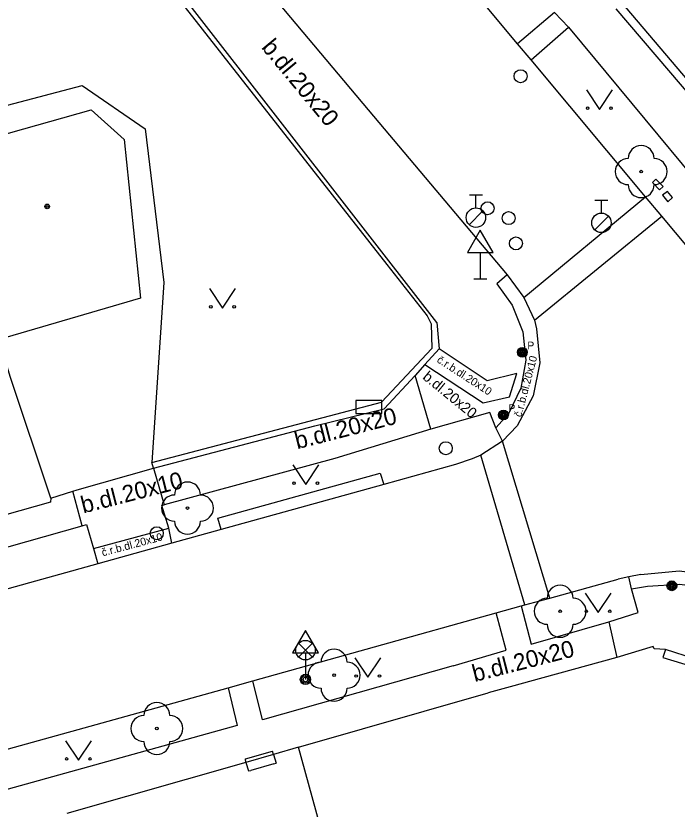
# Model space of a CAD drawing. Extents: x -595546 to -593986, y -1160845 to -1159202.
# Drawn here: x -595239.81 to -595214.37, y -1160581.47 to -1160550.96 of the extents above; entities that cross this region are included whole.
import ezdxf

# ---------------------------------------------------------------- set-up
doc = ezdxf.new("R2010")
doc.units = 0
for name, color, linetype in [('Level 22', 7, 'Continuous'), ('Level 24', 7, 'Continuous'), ('Level 28', 7, 'Continuous'), ('Level 33', 7, 'Continuous'), ('Level 34', 7, 'Continuous'), ('Level 36', 7, 'Continuous'), ('Level 39', 7, 'Continuous'), ('slaboproud - povrch.  znaky a tel. budka skut. velikost', 7, 'Continuous'), ('TM - budovy zdene_ betonove - NP', 7, 'Continuous'), ('TM - budovy zdene_ betonove - VP', 7, 'Continuous'), ('TM - chodniky - VP', 7, 'Continuous'), ('TM - komunikace - VP', 7, 'Continuous'), ('TM - letecke snimky - pomocna linie', 7, 'Continuous'), ('TM - plot drateny_ kovovy - VP', 7, 'Continuous'), ('TM - podezdivka plotu - VP', 7, 'Continuous'), ('TM - popis povrchu', 7, 'Continuous'), ('TM - rozhrani mezi zpev. plochami mezi sebou - VP', 7, 'Continuous'), ('TM - rozhrani ploch obecne - VP', 7, 'Continuous'), ('TM - vjezd na pozemek', 7, 'Continuous'), ('TM - vstup do budovy - zdene_ betonove', 7, 'Continuous'), ('TM - vstup do budovy - zdene_ betonove  - shora neviditelny', 7, 'Continuous'), ('Vrstva 34', 7, 'Continuous')]:
    doc.layers.add(name, color=color, linetype=linetype)

msp = doc.modelspace()

# ---------------------------------------------------------------- linework, layer by layer
at = {"layer": 'Level 22'}
for centre in [(-595215.75, -1160556.95), (-595233.21, -1160569.89), (-595218.87, -1160573.86), (-595227.57, -1160576.32), (-595234.39, -1160578.37)]:
    msp.add_circle(centre, 0.05, dxfattribs=at)
for centre, start, end in [((-595215.75, -1160556.45), 0, 180), ((-595216.25, -1160556.95), 90, 270), ((-595215.25, -1160556.95), 270, 90), ((-595215.75, -1160557.45), 180, 0), ((-595233.21, -1160569.39), 0, 180), ((-595233.71, -1160569.89), 90, 270), ((-595232.71, -1160569.89), 270, 90), ((-595233.21, -1160570.39), 180, 0), ((-595218.87, -1160573.36), 0, 180), ((-595219.37, -1160573.86), 90, 270), ((-595218.37, -1160573.86), 270, 90), ((-595218.87, -1160574.36), 180, 0), ((-595227.57, -1160575.82), 0, 180), ((-595228.07, -1160576.32), 90, 270), ((-595227.07, -1160576.32), 270, 90), ((-595227.57, -1160576.82), 180, 0), ((-595234.39, -1160577.87), 0, 180), ((-595234.89, -1160578.37), 90, 270), ((-595233.89, -1160578.37), 270, 90), ((-595234.39, -1160578.87), 180, 0)]:
    msp.add_arc(centre, 0.5, start, end, dxfattribs=at)
at = {"layer": 'Level 24'}
msp.add_lwpolyline([(-595226.737, -1160566.258), (-595225.737, -1160566.258), (-595225.737, -1160565.758), (-595226.737, -1160565.758)], close=True, dxfattribs=at)
at = {"layer": 'Level 28'}
for p, q in [((-595222.36, -1160557.845), (-595221.86, -1160557.845)), ((-595222.11, -1160558.345), (-595222.11, -1160557.845)), ((-595217.53, -1160558.045), (-595217.03, -1160558.045)), ((-595217.28, -1160558.545), (-595217.28, -1160558.045)), ((-595222.368, -1160558.992), (-595221.838, -1160558.462)), ((-595217.538, -1160559.192), (-595217.008, -1160558.662))]:
    msp.add_line(p, q, dxfattribs=at)
for centre, radius in [((-595220.39, -1160553.28), 0.25), ((-595221.66, -1160558.36), 0.25), ((-595222.11, -1160558.72), 0.375), ((-595220.85, -1160558.74), 0.25), ((-595217.28, -1160558.92), 0.375), ((-595220.57, -1160559.71), 0.25), ((-595223.27, -1160567.59), 0.25), ((-595234.39, -1160570.86), 0.25)]:
    msp.add_circle(centre, radius, dxfattribs=at)
at = {"layer": 'Level 33'}
for p, q in [((-595228.935, -1160575.62), (-595228.405, -1160575.09)), ((-595228.935, -1160575.09), (-595228.405, -1160575.62)), ((-595228.67, -1160575.73), (-595228.67, -1160576.48))]:
    msp.add_line(p, q, dxfattribs=at)
for centre, radius in [((-595228.67, -1160575.355), 0.375), ((-595228.67, -1160576.48), 0.2), ((-595228.67, -1160576.48), 0.145), ((-595228.67, -1160576.48), 0.0876)]:
    msp.add_circle(centre, radius, dxfattribs=at)
at = {"layer": 'Level 34'}
for p, q in [((-595221.94, -1160560.062), (-595221.94, -1160561.08)), ((-595222.19, -1160561.08), (-595221.69, -1160561.08)), ((-595228.67, -1160575.462), (-595228.67, -1160576.48))]:
    msp.add_line(p, q, dxfattribs=at)
for points in [[(-595222.44, -1160560.062), (-595221.44, -1160560.062), (-595221.94, -1160559.196)], [(-595229.17, -1160575.462), (-595228.17, -1160575.462), (-595228.67, -1160574.596)]]:
    msp.add_lwpolyline(points, close=True, dxfattribs=at)
at = {"layer": 'Level 36'}
for points in [[(-595217.86, -1160553.81), (-595217.36, -1160554.56), (-595216.86, -1160553.81)], [(-595232.36, -1160561.45), (-595231.86, -1160562.2), (-595231.36, -1160561.45)], [(-595229.16, -1160568.23), (-595228.66, -1160568.98), (-595228.16, -1160568.23)], [(-595217.91, -1160573.16), (-595217.41, -1160573.91), (-595216.91, -1160573.16)], [(-595226.77, -1160575.65), (-595226.27, -1160576.4), (-595225.77, -1160575.65)], [(-595237.91, -1160578.84), (-595237.41, -1160579.59), (-595236.91, -1160578.84)]]:
    msp.add_lwpolyline(points, dxfattribs=at)
for centre in [(-595217.81, -1160554.51), (-595216.911, -1160554.51), (-595232.31, -1160562.15), (-595231.411, -1160562.15), (-595229.11, -1160568.93), (-595228.211, -1160568.93), (-595217.86, -1160573.86), (-595216.961, -1160573.86), (-595226.72, -1160576.35), (-595225.821, -1160576.35), (-595237.86, -1160579.54), (-595236.961, -1160579.54)]:
    msp.add_circle(centre, 0.05, dxfattribs=at)
at = {"layer": 'Level 39'}
for radius in [0.09, 0.0398]:
    msp.add_circle((-595238.61, -1160558.29), radius, dxfattribs=at)
at = {"layer": 'slaboproud - povrch.  znaky a tel. budka skut. velikost'}
for points in [[(-595215.19, -1160557.24), (-595215.32, -1160557.37)], [(-595215.32, -1160557.37), (-595215.04, -1160557.65)], [(-595214.91, -1160557.52), (-595215.19, -1160557.24)], [(-595215.04, -1160557.65), (-595214.91, -1160557.52)], [(-595214.74, -1160557.71), (-595214.93, -1160557.86)], [(-595214.93, -1160557.86), (-595214.73, -1160558.11)], [(-595214.54, -1160557.94), (-595214.74, -1160557.71)], [(-595214.73, -1160558.11), (-595214.54, -1160557.94)]]:
    msp.add_lwpolyline(points, dxfattribs=at)
at = {"layer": 'TM - budovy zdene_ betonove - NP'}
for points in [[(-595214.82, -1160575.33), (-595214.92, -1160575.64)], [(-595229.9, -1160579.37), (-595229.8, -1160579.7)], [(-595230.96, -1160579.67), (-595230.86, -1160580)], [(-595229.89, -1160579.73), (-595229.8, -1160579.7)], [(-595230.86, -1160580), (-595230.77, -1160579.98)]]:
    msp.add_lwpolyline(points, dxfattribs=at)
at = {"layer": 'TM - budovy zdene_ betonove - VP'}
for points in [[(-595238.47, -1160569.51), (-595240.03, -1160564.83), (-595240.47, -1160563.41)], [(-595238.47, -1160569.51), (-595238.48, -1160569.66)], [(-595238.48, -1160569.66), (-595246.66, -1160571.97)], [(-595215.29, -1160575.21), (-595216.69, -1160575.64)], [(-595215.25, -1160575.3), (-595215.29, -1160575.21)], [(-595214.82, -1160575.33), (-595215.25, -1160575.3)], [(-595213.7, -1160575.69), (-595214.82, -1160575.33)], [(-595216.69, -1160575.64), (-595219.54, -1160576.42)], [(-595220.79, -1160576.77), (-595221.64, -1160577)], [(-595228.94, -1160579.09), (-595221.64, -1160577)], [(-595228.94, -1160579.09), (-595229.9, -1160579.37)], [(-595226.01, -1160589.72), (-595228.94, -1160579.09)], [(-595229.9, -1160579.37), (-595230.96, -1160579.67)], [(-595230.96, -1160579.67), (-595237.85, -1160581.64)]]:
    msp.add_lwpolyline(points, dxfattribs=at)
at = {"layer": 'TM - chodniky - VP'}
for points in [[(-595219.08, -1160550.83), (-595220.51, -1160552.04)], [(-595219.99, -1160552.65), (-595218.55, -1160551.4)], [(-595218.55, -1160551.4), (-595210.74, -1160560.81)], [(-595221.58, -1160566.22), (-595223.85, -1160566.86)], [(-595221.34, -1160566.8), (-595221.58, -1160566.22)], [(-595221.09, -1160567.32), (-595221.34, -1160566.8)], [(-595223.85, -1160566.86), (-595227.54, -1160567.98)], [(-595227.54, -1160567.98), (-595234.11, -1160569.76)], [(-595234.2, -1160569.79), (-595234.11, -1160569.76)], [(-595233.93, -1160570.66), (-595234.2, -1160569.79)], [(-595247.15, -1160573.37), (-595237.26, -1160570.57)], [(-595237.26, -1160570.57), (-595237.1, -1160570.52)], [(-595237.1, -1160570.52), (-595236.83, -1160571.44)], [(-595233.81, -1160571.24), (-595233.93, -1160570.66)], [(-595236.83, -1160571.44), (-595236.66, -1160572.03)], [(-595216.12, -1160573), (-595216.23, -1160572.54)], [(-595215.87, -1160573.91), (-595216.12, -1160573)], [(-595220.37, -1160573.65), (-595219.98, -1160575.12)], [(-595220.94, -1160575.36), (-595221.33, -1160573.92)], [(-595217, -1160574.27), (-595215.87, -1160573.91)], [(-595219.98, -1160575.12), (-595217, -1160574.27)], [(-595222.98, -1160575.96), (-595220.94, -1160575.36)], [(-595222.98, -1160575.96), (-595230.32, -1160578.03)], [(-595230.32, -1160578.03), (-595230.69, -1160576.53)], [(-595231.65, -1160576.8), (-595231.3, -1160578.25)], [(-595231.3, -1160578.25), (-595243.44, -1160581.63)]]:
    msp.add_lwpolyline(points, dxfattribs=at)
at = {"layer": 'TM - komunikace - VP'}
for points in [[(-595232.03, -1160547.7), (-595226.26, -1160554.57)], [(-595220.51, -1160552.04), (-595221.87, -1160550.41)], [(-595219.99, -1160552.65), (-595220.51, -1160552.04)], [(-595215.58, -1160557.92), (-595219.99, -1160552.65)], [(-595226.26, -1160554.57), (-595220.91, -1160560.92)], [(-595214.95, -1160558.67), (-595215.58, -1160557.92)], [(-595212.2, -1160561.96), (-595214.95, -1160558.67)], [(-595220.91, -1160560.92), (-595220.27, -1160561.79)], [(-595220.27, -1160561.79), (-595219.86, -1160562.66)], [(-595219.86, -1160562.66), (-595219.78, -1160563), (-595219.65, -1160564.3), (-595219.91, -1160565.58), (-595220.52, -1160566.73)], [(-595220.52, -1160566.73), (-595221.09, -1160567.32)], [(-595221.09, -1160567.32), (-595221.92, -1160567.86)], [(-595222.26, -1160568), (-595222.9, -1160568.21)], [(-595221.92, -1160567.86), (-595222.26, -1160568)], [(-595222.9, -1160568.21), (-595225.65, -1160568.98)], [(-595225.65, -1160568.98), (-595231.92, -1160570.72)], [(-595231.92, -1160570.72), (-595233.81, -1160571.24)], [(-595233.81, -1160571.24), (-595236.66, -1160572.03)], [(-595236.66, -1160572.03), (-595240.3, -1160573.05)], [(-595215.76, -1160572.44), (-595214.29, -1160572.3), (-595212.83, -1160572.48)], [(-595219.27, -1160573.35), (-595216.63, -1160572.62)], [(-595216.23, -1160572.54), (-595216.63, -1160572.62)], [(-595215.76, -1160572.44), (-595216.23, -1160572.54)], [(-595220.23, -1160573.61), (-595219.27, -1160573.35)], [(-595221.33, -1160573.92), (-595220.37, -1160573.65)], [(-595220.37, -1160573.65), (-595220.23, -1160573.61)], [(-595230.69, -1160576.53), (-595221.33, -1160573.92)], [(-595231.65, -1160576.8), (-595230.69, -1160576.53)], [(-595243.8, -1160580.18), (-595231.65, -1160576.8)]]:
    msp.add_lwpolyline(points, dxfattribs=at)
at = {"layer": 'TM - letecke snimky - pomocna linie'}
for points in [[(-595243.02, -1160555.15), (-595237.26, -1160553.64), (-595234.84, -1160555.31), (-595234.12, -1160561.22), (-595234.58, -1160568.14)], [(-595242.7, -1160556.2), (-595236.92, -1160554.57), (-595235.65, -1160555.71), (-595235.02, -1160561.82), (-595240.47, -1160563.41)]]:
    msp.add_lwpolyline(points, dxfattribs=at)
at = {"layer": 'TM - plot drateny_ kovovy - VP'}
for points in [[(-595239.75, -1160542.44), (-595238.3, -1160544.26), (-595225.54, -1160560.52)], [(-595211.49, -1160556.33), (-595216.36, -1160550.6), (-595213.17, -1160547.65)], [(-595225.54, -1160560.52), (-595223.98, -1160562.5)], [(-595223.98, -1160562.5), (-595223.83, -1160562.81), (-595223.81, -1160563.75), (-595225.74, -1160565.82)], [(-595234.58, -1160568.14), (-595225.74, -1160565.82)]]:
    msp.add_lwpolyline(points, dxfattribs=at)
at = {"layer": 'TM - podezdivka plotu - VP'}
for points in [[(-595223.62, -1160562.75), (-595232.93, -1160550.79), (-595239.31, -1160542.48)], [(-595216.72, -1160550.69), (-595207.64, -1160561.32)], [(-595223.62, -1160562.75), (-595223.53, -1160563.77)], [(-595223.53, -1160563.77), (-595224.08, -1160564.37)], [(-595224.08, -1160564.37), (-595224.45, -1160564.79)], [(-595225.64, -1160566.07), (-595224.45, -1160564.79)], [(-595228.31, -1160566.73), (-595225.64, -1160566.07)], [(-595234.52, -1160568.35), (-595228.31, -1160566.73)], [(-595234.52, -1160568.35), (-595234.58, -1160568.14)]]:
    msp.add_lwpolyline(points, dxfattribs=at)
at = {"layer": 'TM - rozhrani mezi zpev. plochami mezi sebou - VP'}
for points in [[(-595218.55, -1160551.4), (-595219.08, -1160550.83)], [(-595220.91, -1160560.92), (-595221.31, -1160561.27)], [(-595221.31, -1160561.27), (-595220.71, -1160562.09)], [(-595220.71, -1160562.09), (-595220.3, -1160563.11), (-595220.19, -1160564.2)], [(-595221.68, -1160565), (-595223.53, -1160563.77)], [(-595224.08, -1160564.37), (-595221.83, -1160565.84)], [(-595220.19, -1160564.2), (-595220.38, -1160565.28)], [(-595223.85, -1160566.86), (-595224.45, -1160564.79)], [(-595220.54, -1160564.72), (-595221.68, -1160565)], [(-595220.82, -1160565.61), (-595220.54, -1160564.72)], [(-595220.38, -1160565.28), (-595220.86, -1160566.26)], [(-595221.83, -1160565.84), (-595220.82, -1160565.61)], [(-595220.86, -1160566.26), (-595221.34, -1160566.8)], [(-595234.52, -1160568.35), (-595234.11, -1160569.76)], [(-595237.26, -1160570.57), (-595237.62, -1160569.24)], [(-595236.83, -1160571.44), (-595233.93, -1160570.66)], [(-595216.12, -1160573), (-595215.51, -1160572.9)], [(-595215.51, -1160572.9), (-595214.26, -1160572.82), (-595213.02, -1160572.98)], [(-595217, -1160574.27), (-595216.69, -1160575.64)]]:
    msp.add_lwpolyline(points, dxfattribs=at)
at = {"layer": 'TM - rozhrani ploch obecne - VP'}
for points in [[(-595220.27, -1160561.79), (-595215.58, -1160557.92)], [(-595219.86, -1160562.66), (-595214.95, -1160558.67)], [(-595219.27, -1160573.35), (-595221.09, -1160567.32)], [(-595220.23, -1160573.61), (-595221.92, -1160567.86)], [(-595231.92, -1160570.72), (-595232.04, -1160570.28), (-595225.79, -1160568.55), (-595225.65, -1160568.98)], [(-595230.98, -1160579.54), (-595229.94, -1160579.24)], [(-595229.9, -1160579.37), (-595229.94, -1160579.24)], [(-595230.96, -1160579.67), (-595230.98, -1160579.54)]]:
    msp.add_lwpolyline(points, dxfattribs=at)
at = {"layer": 'TM - vjezd na pozemek'}
for points in [[(-595237.46, -1160569.19), (-595234.52, -1160568.35)], [(-595238.47, -1160569.51), (-595237.62, -1160569.24)], [(-595237.62, -1160569.24), (-595237.46, -1160569.19)]]:
    msp.add_lwpolyline(points, dxfattribs=at)
at = {"layer": 'TM - vstup do budovy - zdene_ betonove'}
msp.add_lwpolyline([(-595219.54, -1160576.42), (-595220.79, -1160576.77)], dxfattribs=at)
at = {"layer": 'TM - vstup do budovy - zdene_ betonove  - shora neviditelny'}
for points in [[(-595214.92, -1160575.64), (-595213.78, -1160575.98)], [(-595229.89, -1160579.73), (-595230.77, -1160579.98)]]:
    msp.add_lwpolyline(points, dxfattribs=at)
at = {"layer": 'Vrstva 34'}
for centre, radius in [((-595220.32, -1160563.9), 0.188), ((-595220.32, -1160563.9), 0.15), ((-595220.32, -1160563.9), 0.113), ((-595220.32, -1160563.9), 0.075), ((-595220.32, -1160563.9), 0.0375), ((-595221.05, -1160566.31), 0.188), ((-595221.05, -1160566.31), 0.15), ((-595221.05, -1160566.31), 0.113), ((-595221.05, -1160566.31), 0.075), ((-595221.05, -1160566.31), 0.0375), ((-595214.57, -1160572.88), 0.188), ((-595214.57, -1160572.88), 0.15), ((-595214.57, -1160572.88), 0.113), ((-595214.57, -1160572.88), 0.075), ((-595214.57, -1160572.88), 0.0375)]:
    msp.add_circle(centre, radius, dxfattribs=at)

# ---------------------------------------------------------------- texts
at = {"layer": 'TM - popis povrchu'}
for s, height, rotation, p in [('b.dl.20x20', 0.65, 309.5841, (-595230.39, -1160552.18)), ('č.r.b.dl.20x10', 0.3, 327, (-595223.64, -1160564.26)), ('č.r.b.dl.20x10', 0.3, 75.2725, (-595220.36, -1160566.41)), ('b.dl.20x20', 0.4, 320.7526, (-595224.19, -1160564.9)), ('b.dl.20x20', 0.65, 14.3682, (-595228.99, -1160567.63)), ('b.dl.20x10', 0.65, 14.3682, (-595237.22, -1160570.1)), ('č.r.b.dl.20x10', 0.3, 14.9751, (-595236.47, -1160571.75)), ('b.dl.20x20', 0.65, 14.3682, (-595222.16, -1160576.58))]:
    msp.add_text(s, height=height, rotation=rotation, dxfattribs=at).set_placement(p)
at = {"layer": 'Vrstva 34'}
for p in [(-595220.132, -1160563.787), (-595220.862, -1160566.197)]:
    msp.add_text('P', height=0.3, dxfattribs=at).set_placement(p)

doc.saveas('drawing.dxf')
